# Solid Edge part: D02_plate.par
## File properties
Author: mokuno
Template: jis part.par
Last saved by: edge
Revision: 9
Application: Solid Edge
文書内容のタイプ: 0
Accuracy: 0.990
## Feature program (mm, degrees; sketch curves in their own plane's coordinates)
sketch for "unnamed Protrusion 1" plane through (0, 0, 0) normal (0, 0, 1) x-axis (1, 0, 0)
  line (-100, 40) -> (100, 40)
  line (100, 40) -> (100, -40)
  line (100, -40) -> (-100, -40)
  line (-100, -40) -> (-100, 40)
  dimension (linear) = 100
  dimension (linear) = 100
extrude "unnamed Protrusion 1" add finite 30 along -normal
sketch for "Hole_1" plane through (0, 0, 0) normal (0, 0, 1) x-axis (1, 0, 0)
  hole centre (-60, -20) bore radius 6
hole "Hole_1" diameter 12 through
pattern "unnamed Pattern 1" of "Hole_1"
pattern "unnamed Pattern 2"
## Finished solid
Body 1: solid body, 14 faces, 28 edges, 8 vertices.
  Faces by surface: cylinder 8, plane 6
  Edges by curve: circle 16, line 12
Bounding box of the edges (mm): 200.000 x 80.000 x 30.000, from (-100, -40, -30) to (100, 40, 0).
Cylindrical faces by radius (mm): R6 x8
Planar faces by outward normal: +x 1, +y 1, +z 1, -x 1, -y 1, -z 1
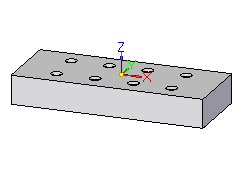
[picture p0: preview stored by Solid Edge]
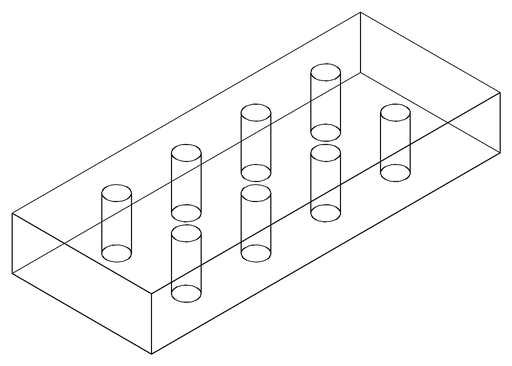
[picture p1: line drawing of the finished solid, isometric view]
